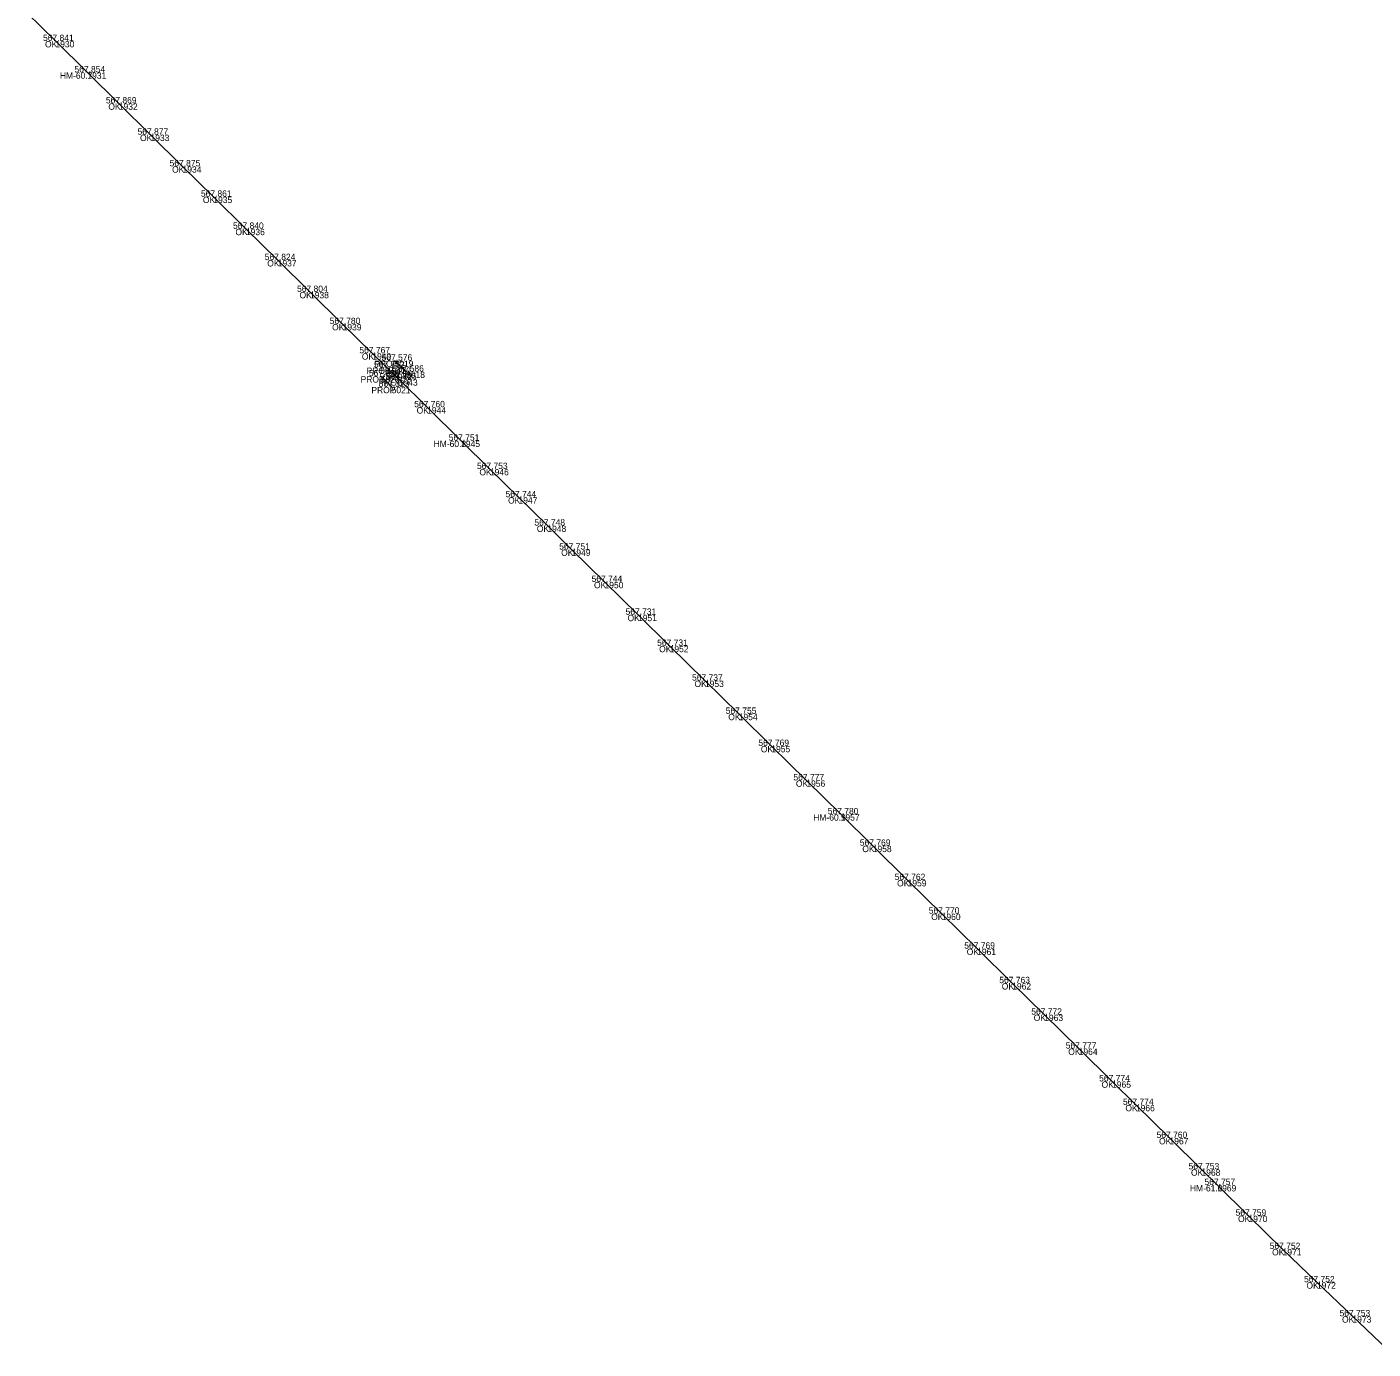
# Model space of a CAD drawing. Extents: x -631472 to -620808, y -1122356 to -1115125.
# Drawn here: x -622556.8 to -622302.2, y -1121483.7 to -1121233.6 of the extents above; entities that cross this region are included whole.
import ezdxf

# ---------------------------------------------------------------- set-up
doc = ezdxf.new("R2010")
doc.units = 0
for name, color, linetype in [('Vrstva 1', 7, 'Continuous'), ('Vrstva 18', 7, 'Continuous'), ('Vrstva 60', 7, 'Continuous'), ('Vrstva 61', 7, 'Continuous'), ('Vrstva 62', 7, 'Continuous')]:
    doc.layers.add(name, color=color, linetype=linetype)

msp = doc.modelspace()

# ---------------------------------------------------------------- linework, layer by layer
at = {"layer": 'Vrstva 1'}
msp.add_lwpolyline([(-622556.81, -1121230.96), (-622551.41, -1121236.29), (-622545.37, -1121242.24), (-622539.43, -1121248.1), (-622533.43, -1121254.02), (-622527.37, -1121260), (-622521.55, -1121265.75), (-622515.38, -1121271.82), (-622509.38, -1121277.74), (-622503.27, -1121283.76), (-622497.1, -1121289.84), (-622491.48, -1121295.37), (-622488.74, -1121298.06), (-622487.54, -1121299.24), (-622486.47, -1121300.29), (-622481.11, -1121305.57), (-622474.68, -1121311.9), (-622469.24, -1121317.26), (-622463.83, -1121322.59), (-622458.37, -1121327.96), (-622453.78, -1121332.49), (-622447.56, -1121338.61), (-622441.22, -1121344.84), (-622435.24, -1121350.71), (-622428.56, -1121357.29), (-622422.17, -1121363.57), (-622416.01, -1121369.64), (-622409.38, -1121376.17), (-622402.88, -1121382.57), (-622396.82, -1121388.53), (-622390.23, -1121395.02), (-622383.78, -1121401.38), (-622377.07, -1121407.99), (-622370.44, -1121414.52), (-622364.39, -1121420.47), (-622357.87, -1121426.9), (-622351.55, -1121433.11), (-622347.05, -1121437.55), (-622340.69, -1121443.81), (-622334.64, -1121449.75), (-622331.63, -1121452.72), (-622325.75, -1121458.51), (-622319.3, -1121464.82), (-622312.8, -1121471.11), (-622306.08, -1121477.54), (-622299.51, -1121483.74)], dxfattribs=at)
at = {"layer": 'Vrstva 18'}
for p, q in [((-622487.28, -1121296.75), (-622485.09, -1121298.83)), ((-622489.87, -1121299.7), (-622487.82, -1121301.72))]:
    msp.add_line(p, q, dxfattribs=at)
at = {"layer": 'Vrstva 60'}
for p, q in [((-622551.41, -1121236.29), (-622551.41, -1121236.29)), ((-622545.37, -1121242.24), (-622545.37, -1121242.24)), ((-622539.43, -1121248.1), (-622539.43, -1121248.1)), ((-622533.43, -1121254.02), (-622533.43, -1121254.02)), ((-622527.37, -1121260), (-622527.37, -1121260)), ((-622521.55, -1121265.75), (-622521.55, -1121265.75)), ((-622515.38, -1121271.82), (-622515.38, -1121271.82)), ((-622509.38, -1121277.74), (-622509.38, -1121277.74)), ((-622503.27, -1121283.76), (-622503.27, -1121283.76)), ((-622497.1, -1121289.84), (-622497.1, -1121289.84)), ((-622491.48, -1121295.37), (-622491.48, -1121295.37)), ((-622488.74, -1121298.06), (-622488.74, -1121298.06)), ((-622487.54, -1121299.24), (-622487.54, -1121299.24)), ((-622486.47, -1121300.29), (-622486.47, -1121300.29)), ((-622481.11, -1121305.57), (-622481.11, -1121305.57)), ((-622474.68, -1121311.9), (-622474.68, -1121311.9)), ((-622469.24, -1121317.26), (-622469.24, -1121317.26)), ((-622463.83, -1121322.59), (-622463.83, -1121322.59)), ((-622458.37, -1121327.96), (-622458.37, -1121327.96)), ((-622453.78, -1121332.49), (-622453.78, -1121332.49)), ((-622447.56, -1121338.61), (-622447.56, -1121338.61)), ((-622441.22, -1121344.84), (-622441.22, -1121344.84)), ((-622435.24, -1121350.71), (-622435.24, -1121350.71)), ((-622428.56, -1121357.29), (-622428.56, -1121357.29)), ((-622422.17, -1121363.57), (-622422.17, -1121363.57)), ((-622416.01, -1121369.64), (-622416.01, -1121369.64)), ((-622409.38, -1121376.17), (-622409.38, -1121376.17)), ((-622402.88, -1121382.57), (-622402.88, -1121382.57)), ((-622396.82, -1121388.53), (-622396.82, -1121388.53)), ((-622390.23, -1121395.02), (-622390.23, -1121395.02)), ((-622383.78, -1121401.38), (-622383.78, -1121401.38)), ((-622377.07, -1121407.99), (-622377.07, -1121407.99)), ((-622370.44, -1121414.52), (-622370.44, -1121414.52)), ((-622364.39, -1121420.47), (-622364.39, -1121420.47)), ((-622357.87, -1121426.9), (-622357.87, -1121426.9)), ((-622351.55, -1121433.11), (-622351.55, -1121433.11)), ((-622347.05, -1121437.55), (-622347.05, -1121437.55)), ((-622340.69, -1121443.81), (-622340.69, -1121443.81)), ((-622334.64, -1121449.75), (-622334.64, -1121449.75)), ((-622331.63, -1121452.72), (-622331.63, -1121452.72)), ((-622325.75, -1121458.51), (-622325.75, -1121458.51)), ((-622319.3, -1121464.82), (-622319.3, -1121464.82)), ((-622312.8, -1121471.11), (-622312.8, -1121471.11)), ((-622306.08, -1121477.54), (-622306.08, -1121477.54))]:
    msp.add_line(p, q, dxfattribs=at)

# ---------------------------------------------------------------- texts
for s, p in [('1930', (-622551.41, -1121237.49)), ('1931', (-622545.37, -1121243.44)), ('1932', (-622539.43, -1121249.3)), ('1933', (-622533.43, -1121255.22)), ('1934', (-622527.37, -1121261.2)), ('1935', (-622521.55, -1121266.95)), ('1936', (-622515.38, -1121273.02)), ('1937', (-622509.38, -1121278.94)), ('1938', (-622503.27, -1121284.96)), ('1939', (-622497.1, -1121291.04)), ('1940', (-622491.48, -1121296.57)), ('5019', (-622487.28, -1121297.95)), ('1941', (-622488.74, -1121299.26)), ('1942', (-622487.54, -1121300.44)), ('5018', (-622485.09, -1121300.03)), ('5020', (-622489.87, -1121300.9)), ('5021', (-622487.82, -1121302.92)), ('1943', (-622486.47, -1121301.49)), ('1944', (-622481.11, -1121306.77)), ('1945', (-622474.68, -1121313.1)), ('1946', (-622469.24, -1121318.46)), ('1947', (-622463.83, -1121323.79)), ('1948', (-622458.37, -1121329.16)), ('1949', (-622453.78, -1121333.69)), ('1950', (-622447.56, -1121339.81)), ('1951', (-622441.22, -1121346.04)), ('1952', (-622435.24, -1121351.91)), ('1953', (-622428.56, -1121358.49)), ('1954', (-622422.17, -1121364.77)), ('1955', (-622416.01, -1121370.84)), ('1956', (-622409.38, -1121377.37)), ('1957', (-622402.88, -1121383.77)), ('1958', (-622396.82, -1121389.73)), ('1959', (-622390.23, -1121396.22)), ('1960', (-622383.78, -1121402.58)), ('1961', (-622377.07, -1121409.19)), ('1962', (-622370.44, -1121415.72)), ('1963', (-622364.39, -1121421.67)), ('1964', (-622357.87, -1121428.09)), ('1965', (-622351.55, -1121434.31)), ('1966', (-622347.05, -1121438.75)), ('1967', (-622340.69, -1121445.01)), ('1968', (-622334.64, -1121450.95)), ('1969', (-622331.63, -1121453.92)), ('1970', (-622325.75, -1121459.71)), ('1971', (-622319.3, -1121466.02)), ('1972', (-622312.8, -1121472.31)), ('1973', (-622306.08, -1121478.74))]:
    msp.add_text(s, height=1.2, dxfattribs=at).set_placement(p)
at = {"layer": 'Vrstva 61'}
for s, p in [('567.841', (-622553.77, -1121236.29)), ('567.854', (-622547.82, -1121242.24)), ('567.869', (-622541.88, -1121248.1)), ('567.877', (-622535.89, -1121254.02)), ('567.875', (-622529.83, -1121260)), ('567.861', (-622523.9, -1121265.75)), ('567.840', (-622517.83, -1121271.82)), ('567.824', (-622511.83, -1121277.74)), ('567.804', (-622505.72, -1121283.76)), ('567.780', (-622499.55, -1121289.84)), ('567.767', (-622493.93, -1121295.37)), ('567.576', (-622489.73, -1121296.75)), ('567.321', (-622492.12, -1121299.7)), ('567.772', (-622491.18, -1121298.06)), ('567.770', (-622489.99, -1121299.24)), ('567.765', (-622488.93, -1121300.29)), ('567.586', (-622487.54, -1121298.83)), ('567.323', (-622490.27, -1121301.72)), ('567.760', (-622483.56, -1121305.57)), ('567.751', (-622477.04, -1121311.9)), ('567.753', (-622471.69, -1121317.26)), ('567.744', (-622466.28, -1121322.59)), ('567.748', (-622460.83, -1121327.96)), ('567.751', (-622456.13, -1121332.49)), ('567.744', (-622450.01, -1121338.61)), ('567.731', (-622443.58, -1121344.84)), ('567.731', (-622437.6, -1121350.71)), ('567.737', (-622431.01, -1121357.29)), ('567.755', (-622424.63, -1121363.57)), ('567.769', (-622418.46, -1121369.64)), ('567.777', (-622411.83, -1121376.17)), ('567.780', (-622405.33, -1121382.57)), ('567.769', (-622399.27, -1121388.53)), ('567.762', (-622392.68, -1121395.02)), ('567.770', (-622386.23, -1121401.38)), ('567.769', (-622379.52, -1121407.99)), ('567.763', (-622372.89, -1121414.52)), ('567.772', (-622366.84, -1121420.47)), ('567.777', (-622360.32, -1121426.9)), ('567.774', (-622354, -1121433.11)), ('567.774', (-622349.5, -1121437.55)), ('567.760', (-622343.14, -1121443.81)), ('567.753', (-622337.09, -1121449.75)), ('567.757', (-622334.08, -1121452.72)), ('567.759', (-622328.2, -1121458.51)), ('567.752', (-622321.75, -1121464.82)), ('567.752', (-622315.25, -1121471.11)), ('567.753', (-622308.53, -1121477.54))]:
    msp.add_text(s, height=1.2, dxfattribs=at).set_placement(p)
at = {"layer": 'Vrstva 62'}
for s, p in [('OK', (-622553.39, -1121237.49)), ('HM-60.7', (-622550.58, -1121243.44)), ('OK', (-622541.41, -1121249.3)), ('OK', (-622535.42, -1121255.22)), ('OK', (-622529.36, -1121261.2)), ('OK', (-622523.53, -1121266.95)), ('OK', (-622517.37, -1121273.02)), ('OK', (-622511.36, -1121278.94)), ('OK', (-622505.25, -1121284.96)), ('OK', (-622499.09, -1121291.04)), ('OK', (-622493.46, -1121296.57)), ('PROP', (-622491.11, -1121297.95)), ('PROP', (-622492.57, -1121299.26)), ('OK', (-622489.52, -1121300.44)), ('PROP', (-622488.92, -1121300.03)), ('PROP', (-622493.7, -1121300.9)), ('PROP', (-622491.66, -1121302.92)), ('PROP', (-622490.31, -1121301.49)), ('OK', (-622483.1, -1121306.77)), ('HM-60.8', (-622479.89, -1121313.1)), ('OK', (-622471.23, -1121318.46)), ('OK', (-622465.81, -1121323.79)), ('OK', (-622460.36, -1121329.16)), ('OK', (-622455.76, -1121333.69)), ('OK', (-622449.55, -1121339.81)), ('OK', (-622443.21, -1121346.04)), ('OK', (-622437.23, -1121351.91)), ('OK', (-622430.54, -1121358.49)), ('OK', (-622424.16, -1121364.77)), ('OK', (-622417.99, -1121370.84)), ('OK', (-622411.36, -1121377.37)), ('HM-60.9', (-622408.08, -1121383.77)), ('OK', (-622398.8, -1121389.73)), ('OK', (-622392.22, -1121396.22)), ('OK', (-622385.77, -1121402.58)), ('OK', (-622379.05, -1121409.19)), ('OK', (-622372.42, -1121415.72)), ('OK', (-622366.38, -1121421.67)), ('OK', (-622359.85, -1121428.09)), ('OK', (-622353.54, -1121434.31)), ('OK', (-622349.04, -1121438.75)), ('OK', (-622342.67, -1121445.01)), ('OK', (-622336.63, -1121450.95)), ('HM-61.0', (-622336.83, -1121453.92)), ('OK', (-622327.73, -1121459.71)), ('OK', (-622321.29, -1121466.02)), ('OK', (-622314.79, -1121472.31)), ('OK', (-622308.06, -1121478.74))]:
    msp.add_text(s, height=1.2, dxfattribs=at).set_placement(p)

doc.saveas('drawing.dxf')
